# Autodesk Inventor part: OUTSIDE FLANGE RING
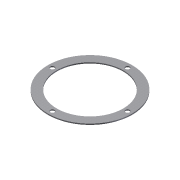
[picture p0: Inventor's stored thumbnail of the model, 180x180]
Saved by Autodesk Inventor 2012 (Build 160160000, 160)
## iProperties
Created: 2011-05
Part Number: OUTSIDE FLANGE RING
Material: Stainless Steel, 440C
Document SubType Name: Modeling
Designer: Dimitris
Mass: 2142.57 g
Surface Area: 1244.07 cm^2
Volume: 276.46 cm^3
Density: 7.75 g/cm^3
Author: Dimitris
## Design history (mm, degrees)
sketch "Sketch1"
  geometry: C1 r 200 at (0, 0); C2 r 240 at (0, 0); 1 further point
  constraints: 2 centre point, 1 coincident
  dimensions: "ID" = 400 diameter of C1; "OD" = 480 diameter of C2
extrude "Extrusion1" new body sketch "Sketch1" distance "d2" = 5; taper "d3" = 0 deg
sketch "Sketch2"
  geometry: C1 r 240 at (0, 0) reference; 3 further points
  constraints: 2 horizontal alignment, 1 coincident, 2 other
  dimensions: "d15" = 20 dimension on C1
hole "Hole1" sketch "Sketch2" at (220, 0) diameter "d5" = 19; stored, may be unused: countersink angle "d9" = 90 deg, drill point angle "d11" = 118 deg; dims "d6" = 6, "d7" = 23.5, "d8" = 2, "d10" = 8
pattern_circular "Circular Pattern1" dims angle "d13" = 360 deg
body "Solid1"
